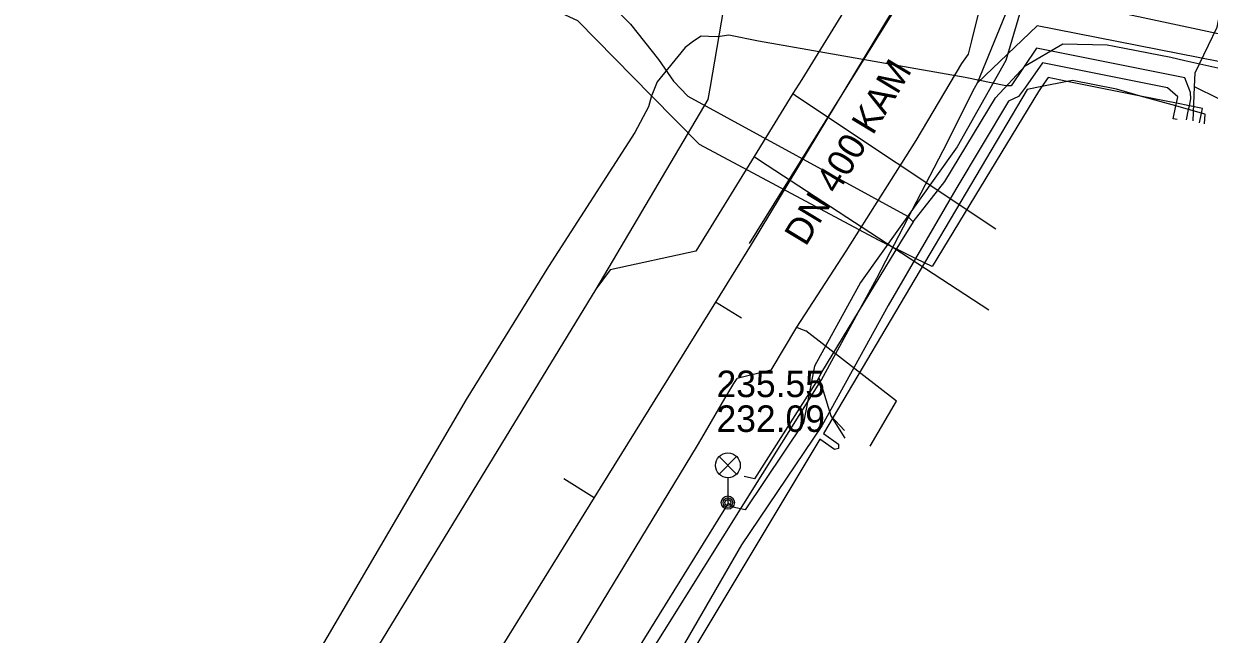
# Model space of a CAD drawing. Extents: x -595540 to -593988, y -1160850 to -1159202.
# Drawn here: x -594774.35 to -594738.56, y -1160797.81 to -1160779.38 of the extents above; entities that cross this region are included whole.
import ezdxf

# ---------------------------------------------------------------- set-up
doc = ezdxf.new("R2010")
doc.units = 0
for name, color, linetype in [('BVK-JEDNOTNA_popisy', 7, 'Continuous'), ('BVK-JEDNOTNA_trasa sítě', 7, 'Continuous'), ('BVK-KANALIZACE_ vyřazená trasa sítě', 7, 'Continuous'), ('BVK-VODOVOD_trasa sítě', 7, 'Continuous'), ('BVK-VODOVOD_trasa zrušené sítě', 7, 'Continuous'), ('CETIN_kabel podzemní', 7, 'Continuous'), ('DESTOVA_trasa neprovozované sítě', 7, 'Continuous'), ('DSP-SDEL-VODAFONE_kabel', 7, 'Continuous'), ('EON-NN_kabel', 7, 'Continuous'), ('EON-NN_kabel zrušené sítě', 7, 'Continuous'), ('INNOGY-STL_trasa sítě', 7, 'Continuous'), ('JEDNOTNA_trasa neprovozované sítě', 7, 'Continuous'), ('TSB_kabel VO', 7, 'Continuous'), ('TSB_lampy VO', 7, 'Continuous')]:
    doc.layers.add(name, color=color, linetype=linetype)

msp = doc.modelspace()

# ---------------------------------------------------------------- linework, layer by layer
at = {"layer": 'BVK-JEDNOTNA_popisy'}
msp.add_line((-594753.433, -1160790.778), (-594753.433, -1160790.778), dxfattribs=at)
at = {"layer": 'BVK-JEDNOTNA_trasa sítě'}
for points in [[(-594745.775, -1160775.227), (-594745.789, -1160775.232), (-594745.812, -1160775.241), (-594745.84, -1160775.257), (-594745.863, -1160775.272), (-594745.883, -1160775.288), (-594745.898, -1160775.303), (-594745.912, -1160775.318), (-594746.704, -1160776.629), (-594752.386, -1160786.049)], [(-594752.386, -1160786.049), (-594753.463, -1160787.785), (-594757.122, -1160793.683), (-594764.332, -1160805.306), (-594769.888, -1160814.261)]]:
    msp.add_lwpolyline(points, dxfattribs=at)
at = {"layer": 'BVK-KANALIZACE_ vyřazená trasa sítě'}
msp.add_lwpolyline([(-594745.801, -1160774.946), (-594745.875, -1160775.44), (-594752.447, -1160786.011)], dxfattribs=at)
at = {"layer": 'BVK-VODOVOD_trasa sítě'}
for points in [[(-594747.47, -1160774.37), (-594747.57, -1160774.94), (-594747.76, -1160776.02), (-594749.36, -1160778.62), (-594750.86, -1160781.06), (-594751.13, -1160781.49), (-594752.3, -1160783.39), (-594754.06, -1160786.25), (-594756.64, -1160786.81), (-594757.08, -1160787.39)], [(-594751.13, -1160781.49), (-594750.987, -1160781.586), (-594745, -1160785.57)], [(-594752.3, -1160783.39), (-594752.14, -1160783.5), (-594745.21, -1160788.02)], [(-594757.08, -1160787.39), (-594763.633, -1160798.153), (-594770.99, -1160810.359), (-594771.309, -1160810.888)]]:
    msp.add_lwpolyline(points, dxfattribs=at)
at = {"layer": 'BVK-VODOVOD_trasa zrušené sítě'}
for points in [[(-594752.889, -1160776.966), (-594753.627, -1160781.273), (-594753.694, -1160781.665), (-594757.08, -1160787.39)], [(-594752.854, -1160776.76), (-594751.105, -1160777.06), (-594748.338, -1160777.534), (-594744.47, -1160778.367), (-594742.813, -1160778.71), (-594733.059, -1160780.787), (-594725.645, -1160782.365), (-594724.297, -1160782.652), (-594715.831, -1160784.455), (-594714.122, -1160784.819), (-594710.59, -1160779.855), (-594709.193, -1160778.722), (-594704.095, -1160779.697), (-594702.193, -1160780.06)]]:
    msp.add_lwpolyline(points, dxfattribs=at)
at = {"layer": 'CETIN_kabel podzemní'}
for points in [[(-594745.55, -1160781.16), (-594744.71, -1160779.1), (-594742.31, -1160772.92), (-594741.45, -1160772.11), (-594740.02, -1160771.71), (-594735.36, -1160772.94), (-594734.15, -1160773.2), (-594731.12, -1160773.83), (-594722.34, -1160775.66), (-594716.39, -1160776.68), (-594715.17, -1160776.82)], [(-594759.86, -1160777.07), (-594759.38, -1160777.07), (-594758.1, -1160777.61), (-594757.64, -1160777.91), (-594756.91, -1160778.52), (-594756.03, -1160779.39), (-594755.18, -1160780.46), (-594754.73, -1160781.11), (-594754.3, -1160781.57), (-594747.67, -1160785.19), (-594747.5, -1160785.36)], [(-594696.79, -1160795.86), (-594695.13, -1160789.74), (-594730.35, -1160782.08), (-594743.75, -1160779.44), (-594745.55, -1160781.16)], [(-594747.5, -1160785.36), (-594746.54, -1160784.14), (-594745.01, -1160781.62), (-594744.12, -1160780.65), (-594742.98, -1160779.99), (-594741.64, -1160780.02), (-594741.43, -1160780.06), (-594739.72, -1160780.39), (-594739.3, -1160780.49), (-594734.95, -1160781.46)], [(-594746.59, -1160783.21), (-594745.64, -1160781.33)], [(-594745.64, -1160781.33), (-594745.55, -1160781.16)], [(-594768.65, -1160820.07), (-594763.67, -1160811.4), (-594763.17, -1160810.53), (-594758.9, -1160804.01), (-594757.35, -1160801.44), (-594750.26, -1160790.13), (-594748.59, -1160787.06), (-594746.59, -1160783.21)], [(-594747.5, -1160785.36), (-594747.88, -1160785.97), (-594750.26, -1160789.9), (-594750.34, -1160790.07)], [(-594750.34, -1160790.07), (-594752.29, -1160793.12), (-594752.6, -1160793.05)], [(-594750.34, -1160790.07), (-594750.21, -1160790.46), (-594749.98, -1160791.22), (-594749.56, -1160791.89)]]:
    msp.add_lwpolyline(points, dxfattribs=at)
at = {"layer": 'DESTOVA_trasa neprovozované sítě'}
msp.add_line((-594738.265, -1160781.651), (-594739.004, -1160781.28), dxfattribs=at)
at = {"layer": 'DSP-SDEL-VODAFONE_kabel'}
for points in [[(-594760.26, -1160777.16), (-594758.1, -1160777.61), (-594757.64, -1160777.91), (-594756.91, -1160778.52), (-594756.03, -1160779.39), (-594755.18, -1160780.46), (-594754.73, -1160781.11), (-594754.3, -1160781.57), (-594747.67, -1160785.19), (-594747.5, -1160785.36)], [(-594747.5, -1160785.36), (-594746.54, -1160784.14), (-594745.01, -1160781.62), (-594744.12, -1160780.65), (-594742.98, -1160779.99), (-594741.64, -1160780.02), (-594741.43, -1160780.06), (-594739.72, -1160780.39), (-594739.3, -1160780.49), (-594734.95, -1160781.46)], [(-594747.5, -1160785.36), (-594747.88, -1160785.97), (-594750.26, -1160789.9), (-594750.34, -1160790.07), (-594750.21, -1160790.46), (-594749.98, -1160791.22), (-594749.565, -1160791.663)]]:
    msp.add_lwpolyline(points, dxfattribs=at)
at = {"layer": 'EON-NN_kabel'}
for points in [[(-594738.849, -1160782.372), (-594738.793, -1160782.078), (-594738.766, -1160781.936), (-594739.156, -1160781.858), (-594739.55, -1160781.779), (-594740.636, -1160781.562), (-594742.844, -1160781.122), (-594743.418, -1160781.007), (-594743.608, -1160781.279), (-594743.712, -1160781.427), (-594746.926, -1160786.713), (-594747.153, -1160786.602), (-594747.426, -1160786.468), (-594748.547, -1160785.918), (-594753.95, -1160783.025), (-594755.392, -1160781.559), (-594757.616, -1160779.297), (-594759.588, -1160778.376), (-594763.338, -1160777.631), (-594763.35, -1160777.948), (-594763.663, -1160777.89), (-594763.458, -1160777.609), (-594777.439, -1160775.13)], [(-594739.245, -1160782.281), (-594739.18, -1160781.97), (-594739.156, -1160781.858), (-594739.112, -1160781.649), (-594739.12, -1160781.451), (-594739.291, -1160781.015), (-594743.774, -1160780.12), (-594744.541, -1160781.25), (-594744.703, -1160781.255), (-594745.922, -1160780.999), (-594752.161, -1160779.902), (-594753.06, -1160779.722), (-594753.398, -1160779.775), (-594753.674, -1160779.766), (-594753.892, -1160779.757), (-594754.132, -1160779.905), (-594754.382, -1160780.097), (-594755.228, -1160781.136), (-594755.386, -1160781.539), (-594755.392, -1160781.559), (-594755.491, -1160781.89), (-594755.896, -1160782.663), (-594758.502, -1160786.714), (-594760.994, -1160790.722), (-594766.331, -1160799.853)], [(-594738.7, -1160782.4), (-594738.68, -1160782.11), (-594738.793, -1160782.078), (-594739.18, -1160781.97), (-594739.568, -1160781.861), (-594740.636, -1160781.562), (-594741.36, -1160781.36), (-594742.69, -1160781.09), (-594742.844, -1160781.122), (-594743.608, -1160781.279), (-594744.05, -1160781.37), (-594747.153, -1160786.602), (-594750.208, -1160791.753), (-594749.755, -1160792.073), (-594749.75, -1160792.2), (-594749.871, -1160792.237), (-594750.312, -1160791.926), (-594757.729, -1160804.284)]]:
    msp.add_lwpolyline(points, dxfattribs=at)
at = {"layer": 'EON-NN_kabel zrušené sítě'}
msp.add_lwpolyline([(-594739.528, -1160782.274), (-594739.652, -1160782.247), (-594739.568, -1160781.861), (-594739.55, -1160781.779), (-594739.508, -1160781.584), (-594739.82, -1160781.317), (-594743.596, -1160780.564), (-594744.11, -1160781.297), (-594744.318, -1160781.572), (-594744.615, -1160781.72), (-594746.212, -1160784.379), (-594747.426, -1160786.468), (-594748.251, -1160787.886), (-594750.258, -1160791.517), (-594752.679, -1160795.113), (-594756.797, -1160802.237)], dxfattribs=at)
at = {"layer": 'INNOGY-STL_trasa sítě'}
for points in [[(-594743.568, -1160771.253), (-594743.8, -1160772.148), (-594743.88, -1160772.467), (-594745.731, -1160779.897), (-594745.837, -1160780.301), (-594746.041, -1160780.576), (-594747.412, -1160782.906), (-594749.529, -1160786.25), (-594751.02, -1160788.538), (-594751.789, -1160789.837), (-594752.812, -1160790.094)], [(-594751.02, -1160788.538), (-594750.893, -1160788.592), (-594750.739, -1160788.656)], [(-594748.79, -1160792.13), (-594748, -1160790.77), (-594750.739, -1160788.656)], [(-594784.914, -1160843.241), (-594783.06, -1160840.14), (-594780.74, -1160836.4), (-594776.01, -1160828.52), (-594772.98, -1160823.51), (-594768.81, -1160816.54), (-594768.15, -1160815.47), (-594760.87, -1160803.42), (-594754.036, -1160792.167), (-594753.878, -1160791.893), (-594753.183, -1160790.697), (-594752.91, -1160790.24), (-594752.812, -1160790.094)]]:
    msp.add_lwpolyline(points, dxfattribs=at)
at = {"layer": 'JEDNOTNA_trasa neprovozované sítě'}
for p, q in [((-594752.677, -1160788.274), (-594753.463, -1160787.785)), ((-594758.039, -1160793.112), (-594757.122, -1160793.683))]:
    msp.add_line(p, q, dxfattribs=at)
msp.add_lwpolyline([(-594739.047, -1160782.307), (-594739.004, -1160781.28), (-594738.986, -1160780.863), (-594738.322, -1160779.488), (-594737.78, -1160776.713)], dxfattribs=at)
at = {"layer": 'TSB_kabel VO'}
for points in [[(-594761.554, -1160768.754), (-594761.509, -1160768.229), (-594760.499, -1160768.352), (-594760.448, -1160768.355), (-594760.118, -1160769.165), (-594752.82, -1160770.131), (-594745.299, -1160771.711), (-594742.263, -1160772.232), (-594744.7, -1160780.49), (-594746.17, -1160783.1), (-594749.09, -1160787.19), (-594750.48, -1160789.72), (-594750.81, -1160791.43), (-594752.57, -1160794.06), (-594752.94, -1160793.98), (-594753.08, -1160793.85)], [(-594753.08, -1160793.85), (-594762.07, -1160808.36), (-594783.204, -1160843.241)]]:
    msp.add_lwpolyline(points, dxfattribs=at)
at = {"layer": 'TSB_lampy VO'}
for p, q in [((-594753.355, -1160792.978), (-594752.825, -1160792.448)), ((-594753.355, -1160792.448), (-594752.825, -1160792.978)), ((-594753.355, -1160792.978), (-594752.825, -1160792.448)), ((-594753.355, -1160792.448), (-594752.825, -1160792.978)), ((-594753.09, -1160793.088), (-594753.09, -1160793.838)), ((-594753.09, -1160793.088), (-594753.09, -1160793.838))]:
    msp.add_line(p, q, dxfattribs=at)
for centre, radius in [((-594753.09, -1160792.713), 0.375), ((-594753.09, -1160792.713), 0.375), ((-594753.09, -1160793.838), 0.2), ((-594753.09, -1160793.838), 0.2), ((-594753.09, -1160793.838), 0.145), ((-594753.09, -1160793.838), 0.145), ((-594753.09, -1160793.838), 0.0876), ((-594753.09, -1160793.838), 0.0876)]:
    msp.add_circle(centre, radius, dxfattribs=at)

# ---------------------------------------------------------------- texts
at = {"layer": 'BVK-JEDNOTNA_popisy'}
msp.add_text('DN 400 KAM', height=0.8, rotation=58.9023, dxfattribs=at).set_placement((-594750.74, -1160786.13))
for s, p in [('235.55', (-594753.433, -1160790.653)), ('232.09', (-594753.433, -1160791.703))]:
    msp.add_text(s, height=0.8, dxfattribs=at).set_placement(p)

doc.saveas('drawing.dxf')
